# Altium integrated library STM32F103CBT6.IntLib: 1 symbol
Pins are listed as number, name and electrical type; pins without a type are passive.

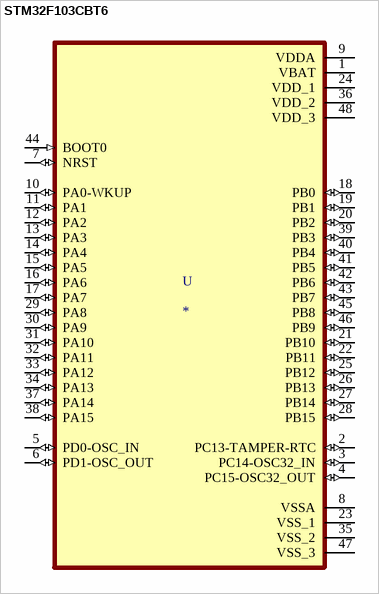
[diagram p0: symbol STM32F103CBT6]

## STM32F103CBT6
designator U
ARMÂ® CortexÂ®-M3 STM32F1 Microcontroller IC 32-Bit 72MHz 128KB _128K x 8_ FLASH; MP: STM32F103CBT6; MF: STMicroelectronics
footprint QFP50P900X900X160-48N
pins: 1 VBAT (power), 2 PC13-TAMPER-RTC (io), 3 PC14-OSC32_IN (io), 4 PC15-OSC32_OUT (io), 5 PD0-OSC_IN (io), 6 PD1-OSC_OUT (io), 7 NRST (io), 8 VSSA (power), 9 VDDA (power), 10 PA0-WKUP (io), 11 PA1 (io), 12 PA2 (io), 13 PA3 (io), 14 PA4 (io), 15 PA5 (io), 16 PA6 (io), 17 PA7 (io), 18 PB0 (io), 19 PB1 (io), 20 PB2 (io), 21 PB10 (io), 22 PB11 (io), 23 VSS_1 (power), 24 VDD_1 (power), 25 PB12 (io), 26 PB13 (io), 27 PB14 (io), 28 PB15 (io), 29 PA8 (io), 30 PA9 (io), 31 PA10 (io), 32 PA11 (io), 33 PA12 (io), 34 PA13 (io), 35 VSS_2 (power), 36 VDD_2 (power), 37 PA14 (io), 38 PA15 (io), 39 PB3 (io), 40 PB4 (io), 41 PB5 (io), 42 PB6 (io), 43 PB7 (io), 44 BOOT0 (in), 45 PB8 (io), 46 PB9 (io), 47 VSS_3 (power), 48 VDD_3 (power)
